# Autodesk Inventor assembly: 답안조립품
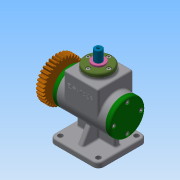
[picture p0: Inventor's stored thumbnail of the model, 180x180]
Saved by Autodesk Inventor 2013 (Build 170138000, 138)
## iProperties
Created: 2019-01
Part Number: 답안조립품
Document SubType Name: Assembly
Designer: Administrator
Mass: 1743.47 g
Surface Area: 1517.22 cm^2
Volume: 492.005 cm^3
Density: 3.54361 g/cm^3
Author: Administrator
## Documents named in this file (18)
- C:\Users\Administrator\Desktop\390107v1005\답안조립품.iam
- C:\Users\Administrator\Desktop\390107v1005\본체.ipt
- C:\Users\Administrator\Desktop\390107v1005\뒤커버.ipt
- C:\Users\Administrator\Desktop\390107v1005\멈춤링.ipt
- C:\Users\Administrator\Desktop\390107v1005\베어링 6203.ipt
- C:\Users\Administrator\Desktop\390107v1005\볼트 M4.ipt
- C:\Users\Administrator\Desktop\390107v1005\부시.ipt
- C:\Users\Administrator\Desktop\390107v1005\상부커버.ipt
- C:\Users\Administrator\Desktop\390107v1005\스퍼기어.ipt
- C:\Users\Administrator\Desktop\390107v1005\스프링와셔.ipt
- C:\Users\Administrator\Desktop\390107v1005\스프링조립용 와셔.ipt
- C:\Users\Administrator\Desktop\390107v1005\슬라이더.ipt
- C:\Users\Administrator\Desktop\390107v1005\앞커버.ipt
- C:\Users\Administrator\Desktop\390107v1005\오일 실 17 30 5.ipt
- C:\Users\Administrator\Desktop\390107v1005\키 4x4x12.ipt
- C:\Users\Administrator\Desktop\390107v1005\편심축.ipt
- C:\Users\Administrator\Desktop\390107v1005\평와셔.ipt
- C:\Users\Administrator\Desktop\390107v1005\가변부품.ipt
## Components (1 placed, 1 different names)
1. 가변부품:1
